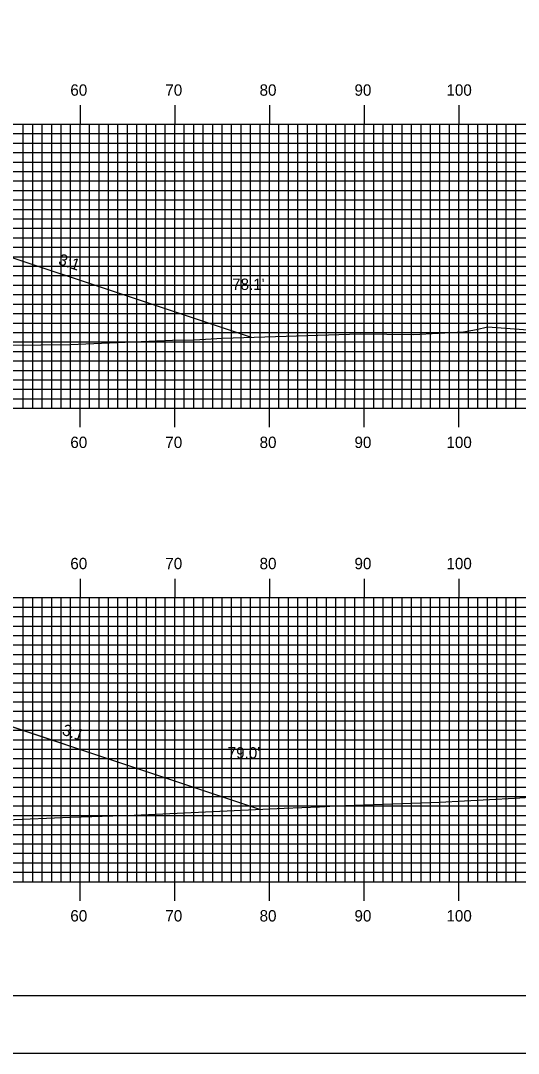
# Model space of a CAD drawing. Extents: x 1762184 to 1762528, y 442591 to 442811.
# Drawn here: x 1762404 to 1762456.5, y 442590.5 to 442699.6 of the extents above; entities that cross this region are included whole.
import ezdxf

# ---------------------------------------------------------------- set-up
doc = ezdxf.new("R2010")
doc.units = 0
for name, color, linetype in [('ANNOTATION', 7, 'Continuous'), ('BORDER', 7, 'Continuous'), ('D_Roadway_Centerline', 7, 'Continuous'), ('D_Roadway_SlopeLines', 7, 'Continuous'), ('D_Text_Standard', 7, 'Continuous'), ('H_V ANNOTATION', 7, 'Continuous'), ('MAJOR', 7, 'Continuous'), ('MINOR', 7, 'Continuous'), ('PLOT BOUNDARY', 7, 'Continuous'), ('S_Roadway_Centerline', 7, 'Continuous')]:
    doc.layers.add(name, color=color, linetype=linetype)

msp = doc.modelspace()

# ---------------------------------------------------------------- linework, layer by layer
at = {"layer": 'BORDER'}
msp.add_lwpolyline([(1762200.67, 442596.67), (1762520.67, 442596.67), (1762520.67, 442806.67), (1762200.67, 442806.67)], close=True, dxfattribs=at)
at = {"layer": 'D_Roadway_Centerline'}
for points in [[(1762388.25, 442679.53), (1762428.32, 442666.17), (1762428.33, 442666.17)], [(1762274.37, 442614.65), (1762275.12, 442614.9), (1762318.99, 442629.52), (1762319.01, 442629.53), (1762325.19, 442631.59), (1762327.27, 442632.28), (1762330.26, 442632.4), (1762330.27, 442632.4), (1762338.27, 442632.72), (1762338.27, 442632.72), (1762350.26, 442633.16), (1762350.27, 442633.16), (1762362.26, 442633.59), (1762362.27, 442633.59), (1762375.55, 442633.06), (1762376.11, 442633.03), (1762385.78, 442630.62), (1762388.12, 442630.03), (1762388.13, 442630.03), (1762429.23, 442616.33)]]:
    msp.add_lwpolyline(points, dxfattribs=at)
at = {"layer": 'D_Roadway_SlopeLines'}
for points in [[(1762376.25, 442682.53), (1762388.25, 442679.53), (1762428.33, 442666.17)], [(1762376.11, 442633.03), (1762388.12, 442630.03), (1762429.23, 442616.33)]]:
    msp.add_lwpolyline(points, dxfattribs=at)
at = {"layer": 'MAJOR'}
for p, q in [((1762410.27, 442690.67), (1762410.27, 442688.67)), ((1762420.27, 442690.67), (1762420.27, 442688.67)), ((1762430.27, 442690.67), (1762430.27, 442688.67)), ((1762440.27, 442690.67), (1762440.27, 442688.67)), ((1762450.27, 442690.67), (1762450.27, 442688.67)), ((1762210.27, 442688.67), (1762490.27, 442688.67)), ((1762210.27, 442688.67), (1762490.27, 442688.67)), ((1762410.27, 442658.67), (1762410.27, 442688.67)), ((1762420.27, 442658.67), (1762420.27, 442688.67)), ((1762430.27, 442658.67), (1762430.27, 442688.67)), ((1762440.27, 442658.67), (1762440.27, 442688.67)), ((1762450.27, 442658.67), (1762450.27, 442688.67)), ((1762210.27, 442683.67), (1762490.27, 442683.67)), ((1762210.27, 442678.67), (1762490.27, 442678.67)), ((1762210.27, 442673.67), (1762490.27, 442673.67)), ((1762210.27, 442668.67), (1762490.27, 442668.67)), ((1762210.27, 442663.67), (1762490.27, 442663.67)), ((1762210.27, 442658.67), (1762490.27, 442658.67)), ((1762210.27, 442658.67), (1762490.27, 442658.67)), ((1762410.27, 442656.66), (1762410.27, 442658.67)), ((1762420.27, 442656.66), (1762420.27, 442658.67)), ((1762430.27, 442656.66), (1762430.27, 442658.67)), ((1762440.27, 442656.66), (1762440.27, 442658.67)), ((1762450.27, 442656.66), (1762450.27, 442658.67)), ((1762410.27, 442640.67), (1762410.27, 442638.67)), ((1762420.27, 442640.67), (1762420.27, 442638.67)), ((1762430.27, 442640.67), (1762430.27, 442638.67)), ((1762440.27, 442640.67), (1762440.27, 442638.67)), ((1762450.27, 442640.67), (1762450.27, 442638.67)), ((1762210.27, 442638.67), (1762490.27, 442638.67)), ((1762210.27, 442638.67), (1762490.27, 442638.67)), ((1762410.27, 442608.67), (1762410.27, 442638.67)), ((1762420.27, 442608.67), (1762420.27, 442638.67)), ((1762430.27, 442608.67), (1762430.27, 442638.67)), ((1762440.27, 442608.67), (1762440.27, 442638.67)), ((1762450.27, 442608.67), (1762450.27, 442638.67)), ((1762210.27, 442633.67), (1762490.27, 442633.67)), ((1762210.27, 442628.67), (1762490.27, 442628.67)), ((1762210.27, 442623.67), (1762490.27, 442623.67)), ((1762210.27, 442618.67), (1762490.27, 442618.67)), ((1762210.27, 442613.67), (1762490.27, 442613.67)), ((1762210.27, 442608.67), (1762490.27, 442608.67)), ((1762210.27, 442608.67), (1762490.27, 442608.67)), ((1762410.27, 442606.66), (1762410.27, 442608.67)), ((1762420.27, 442606.66), (1762420.27, 442608.67)), ((1762430.27, 442606.66), (1762430.27, 442608.67)), ((1762440.27, 442606.66), (1762440.27, 442608.67)), ((1762450.27, 442606.66), (1762450.27, 442608.67))]:
    msp.add_line(p, q, dxfattribs=at)
at = {"layer": 'MINOR'}
for p, q in [((1762404.27, 442658.67), (1762404.27, 442688.67)), ((1762405.27, 442658.67), (1762405.27, 442688.67)), ((1762406.27, 442658.67), (1762406.27, 442688.67)), ((1762407.27, 442658.67), (1762407.27, 442688.67)), ((1762408.27, 442658.67), (1762408.27, 442688.67)), ((1762409.27, 442658.67), (1762409.27, 442688.67)), ((1762411.27, 442658.67), (1762411.27, 442688.67)), ((1762412.27, 442658.67), (1762412.27, 442688.67)), ((1762413.27, 442658.67), (1762413.27, 442688.67)), ((1762414.27, 442658.67), (1762414.27, 442688.67)), ((1762415.27, 442658.67), (1762415.27, 442688.67)), ((1762416.27, 442658.67), (1762416.27, 442688.67)), ((1762417.27, 442658.67), (1762417.27, 442688.67)), ((1762418.27, 442658.67), (1762418.27, 442688.67)), ((1762419.27, 442658.67), (1762419.27, 442688.67)), ((1762421.27, 442658.67), (1762421.27, 442688.67)), ((1762422.27, 442658.67), (1762422.27, 442688.67)), ((1762423.27, 442658.67), (1762423.27, 442688.67)), ((1762424.27, 442658.67), (1762424.27, 442688.67)), ((1762425.27, 442658.67), (1762425.27, 442688.67)), ((1762426.27, 442658.67), (1762426.27, 442688.67)), ((1762427.27, 442658.67), (1762427.27, 442688.67)), ((1762428.27, 442658.67), (1762428.27, 442688.67)), ((1762429.27, 442658.67), (1762429.27, 442688.67)), ((1762431.27, 442658.67), (1762431.27, 442688.67)), ((1762432.27, 442658.67), (1762432.27, 442688.67)), ((1762433.27, 442658.67), (1762433.27, 442688.67)), ((1762434.27, 442658.67), (1762434.27, 442688.67)), ((1762435.27, 442658.67), (1762435.27, 442688.67)), ((1762436.27, 442658.67), (1762436.27, 442688.67)), ((1762437.27, 442658.67), (1762437.27, 442688.67)), ((1762438.27, 442658.67), (1762438.27, 442688.67)), ((1762439.27, 442658.67), (1762439.27, 442688.67)), ((1762441.27, 442658.67), (1762441.27, 442688.67)), ((1762442.27, 442658.67), (1762442.27, 442688.67)), ((1762443.27, 442658.67), (1762443.27, 442688.67)), ((1762444.27, 442658.67), (1762444.27, 442688.67)), ((1762445.27, 442658.67), (1762445.27, 442688.67)), ((1762446.27, 442658.67), (1762446.27, 442688.67)), ((1762447.27, 442658.67), (1762447.27, 442688.67)), ((1762448.27, 442658.67), (1762448.27, 442688.67)), ((1762449.27, 442658.67), (1762449.27, 442688.67)), ((1762451.27, 442658.67), (1762451.27, 442688.67)), ((1762452.27, 442658.67), (1762452.27, 442688.67)), ((1762453.27, 442658.67), (1762453.27, 442688.67)), ((1762454.27, 442658.67), (1762454.27, 442688.67)), ((1762455.27, 442658.67), (1762455.27, 442688.67)), ((1762456.27, 442658.67), (1762456.27, 442688.67)), ((1762210.27, 442687.67), (1762490.27, 442687.67)), ((1762210.27, 442686.67), (1762490.27, 442686.67)), ((1762210.27, 442685.67), (1762490.27, 442685.67)), ((1762210.27, 442684.67), (1762490.27, 442684.67)), ((1762210.27, 442682.67), (1762490.27, 442682.67)), ((1762210.27, 442681.67), (1762490.27, 442681.67)), ((1762210.27, 442680.67), (1762490.27, 442680.67)), ((1762210.27, 442679.67), (1762490.27, 442679.67)), ((1762210.27, 442677.67), (1762490.27, 442677.67)), ((1762210.27, 442676.67), (1762490.27, 442676.67)), ((1762210.27, 442675.67), (1762490.27, 442675.67)), ((1762210.27, 442674.67), (1762490.27, 442674.67)), ((1762210.27, 442672.67), (1762490.27, 442672.67)), ((1762210.27, 442671.67), (1762490.27, 442671.67)), ((1762210.27, 442670.67), (1762490.27, 442670.67)), ((1762210.27, 442669.67), (1762490.27, 442669.67)), ((1762210.27, 442667.67), (1762490.27, 442667.67)), ((1762210.27, 442666.67), (1762490.27, 442666.67)), ((1762210.27, 442665.67), (1762490.27, 442665.67)), ((1762210.27, 442664.67), (1762490.27, 442664.67)), ((1762210.27, 442662.67), (1762490.27, 442662.67)), ((1762210.27, 442661.67), (1762490.27, 442661.67)), ((1762210.27, 442660.67), (1762490.27, 442660.67)), ((1762210.27, 442659.67), (1762490.27, 442659.67)), ((1762404.27, 442608.67), (1762404.27, 442638.67)), ((1762405.27, 442608.67), (1762405.27, 442638.67)), ((1762406.27, 442608.67), (1762406.27, 442638.67)), ((1762407.27, 442608.67), (1762407.27, 442638.67)), ((1762408.27, 442608.67), (1762408.27, 442638.67)), ((1762409.27, 442608.67), (1762409.27, 442638.67)), ((1762411.27, 442608.67), (1762411.27, 442638.67)), ((1762412.27, 442608.67), (1762412.27, 442638.67)), ((1762413.27, 442608.67), (1762413.27, 442638.67)), ((1762414.27, 442608.67), (1762414.27, 442638.67)), ((1762415.27, 442608.67), (1762415.27, 442638.67)), ((1762416.27, 442608.67), (1762416.27, 442638.67)), ((1762417.27, 442608.67), (1762417.27, 442638.67)), ((1762418.27, 442608.67), (1762418.27, 442638.67)), ((1762419.27, 442608.67), (1762419.27, 442638.67)), ((1762421.27, 442608.67), (1762421.27, 442638.67)), ((1762422.27, 442608.67), (1762422.27, 442638.67)), ((1762423.27, 442608.67), (1762423.27, 442638.67)), ((1762424.27, 442608.67), (1762424.27, 442638.67)), ((1762425.27, 442608.67), (1762425.27, 442638.67)), ((1762426.27, 442608.67), (1762426.27, 442638.67)), ((1762427.27, 442608.67), (1762427.27, 442638.67)), ((1762428.27, 442608.67), (1762428.27, 442638.67)), ((1762429.27, 442608.67), (1762429.27, 442638.67)), ((1762431.27, 442608.67), (1762431.27, 442638.67)), ((1762432.27, 442608.67), (1762432.27, 442638.67)), ((1762433.27, 442608.67), (1762433.27, 442638.67)), ((1762434.27, 442608.67), (1762434.27, 442638.67)), ((1762435.27, 442608.67), (1762435.27, 442638.67)), ((1762436.27, 442608.67), (1762436.27, 442638.67)), ((1762437.27, 442608.67), (1762437.27, 442638.67)), ((1762438.27, 442608.67), (1762438.27, 442638.67)), ((1762439.27, 442608.67), (1762439.27, 442638.67)), ((1762441.27, 442608.67), (1762441.27, 442638.67)), ((1762442.27, 442608.67), (1762442.27, 442638.67)), ((1762443.27, 442608.67), (1762443.27, 442638.67)), ((1762444.27, 442608.67), (1762444.27, 442638.67)), ((1762445.27, 442608.67), (1762445.27, 442638.67)), ((1762446.27, 442608.67), (1762446.27, 442638.67)), ((1762447.27, 442608.67), (1762447.27, 442638.67)), ((1762448.27, 442608.67), (1762448.27, 442638.67)), ((1762449.27, 442608.67), (1762449.27, 442638.67)), ((1762451.27, 442608.67), (1762451.27, 442638.67)), ((1762452.27, 442608.67), (1762452.27, 442638.67)), ((1762453.27, 442608.67), (1762453.27, 442638.67)), ((1762454.27, 442608.67), (1762454.27, 442638.67)), ((1762455.27, 442608.67), (1762455.27, 442638.67)), ((1762456.27, 442608.67), (1762456.27, 442638.67)), ((1762210.27, 442637.67), (1762490.27, 442637.67)), ((1762210.27, 442636.67), (1762490.27, 442636.67)), ((1762210.27, 442635.67), (1762490.27, 442635.67)), ((1762210.27, 442634.67), (1762490.27, 442634.67)), ((1762210.27, 442632.67), (1762490.27, 442632.67)), ((1762210.27, 442631.67), (1762490.27, 442631.67)), ((1762210.27, 442630.67), (1762490.27, 442630.67)), ((1762210.27, 442629.67), (1762490.27, 442629.67)), ((1762210.27, 442627.67), (1762490.27, 442627.67)), ((1762210.27, 442626.67), (1762490.27, 442626.67)), ((1762210.27, 442625.67), (1762490.27, 442625.67)), ((1762210.27, 442624.67), (1762490.27, 442624.67)), ((1762210.27, 442622.67), (1762490.27, 442622.67)), ((1762210.27, 442621.67), (1762490.27, 442621.67)), ((1762210.27, 442620.67), (1762490.27, 442620.67)), ((1762210.27, 442619.67), (1762490.27, 442619.67)), ((1762210.27, 442617.67), (1762490.27, 442617.67)), ((1762210.27, 442616.67), (1762490.27, 442616.67)), ((1762210.27, 442615.67), (1762490.27, 442615.67)), ((1762210.27, 442614.67), (1762490.27, 442614.67)), ((1762210.27, 442612.67), (1762490.27, 442612.67)), ((1762210.27, 442611.67), (1762490.27, 442611.67)), ((1762210.27, 442610.67), (1762490.27, 442610.67)), ((1762210.27, 442609.67), (1762490.27, 442609.67))]:
    msp.add_line(p, q, dxfattribs=at)
at = {"layer": 'PLOT BOUNDARY'}
msp.add_lwpolyline([(1762184.48, 442590.55), (1762524.48, 442590.55), (1762524.48, 442810.55), (1762184.48, 442810.55)], close=True, dxfattribs=at)
at = {"layer": 'S_Roadway_Centerline'}
for points in [[(1762399.87, 442665.3), (1762409.23, 442665.41), (1762420.03, 442665.84), (1762422.32, 442665.88), (1762425.29, 442666.07), (1762439.83, 442666.53), (1762445.49, 442666.45), (1762450.76, 442666.72), (1762452.11, 442666.99), (1762453.28, 442667.27), (1762457.58, 442666.94), (1762458.9, 442666.95), (1762461.27, 442667.11), (1762463.39, 442667.18), (1762468.97, 442667.44), (1762480.18, 442667.67), (1762481.78, 442667.72), (1762490.27, 442667.95)], [(1762395.63, 442614.94), (1762409.26, 442615.5), (1762415.97, 442615.69), (1762431.83, 442616.45), (1762435.55, 442616.59), (1762437.19, 442616.69), (1762448.23, 442617.07), (1762456.15, 442617.49), (1762460.13, 442617.74), (1762462.19, 442617.91), (1762464.64, 442617.98), (1762468.88, 442617.9), (1762470.81, 442617.89), (1762472.96, 442618.22), (1762476.25, 442618.35), (1762490.27, 442618.95)]]:
    msp.add_lwpolyline(points, dxfattribs=at)

# ---------------------------------------------------------------- texts
at = {"layer": 'ANNOTATION'}
for rotation, p in [(341.5652, (1762407.89, 442673.89)), (341.565, (1762408.29, 442624.22))]:
    msp.add_text('3:1', height=1.2, rotation=rotation, dxfattribs=at).set_placement(p)
at = {"layer": 'D_Text_Standard'}
for s, p in [("78.1'", (1762426.32, 442671.16)), ("79.0'", (1762425.85, 442621.68))]:
    msp.add_text(s, height=1.2, dxfattribs=at).set_placement(p)
at = {"layer": 'H_V ANNOTATION'}
for s, p in [('60', (1762409.24, 442691.67)), ('70', (1762419.27, 442691.67)), ('80', (1762429.22, 442691.67)), ('90', (1762439.24, 442691.67)), ('100', (1762448.95, 442691.67)), ('60', (1762409.24, 442654.47)), ('70', (1762419.27, 442654.47)), ('80', (1762429.22, 442654.47)), ('90', (1762439.24, 442654.47)), ('100', (1762448.95, 442654.47)), ('60', (1762409.24, 442641.67)), ('70', (1762419.27, 442641.67)), ('80', (1762429.22, 442641.67)), ('90', (1762439.24, 442641.67)), ('100', (1762448.95, 442641.67)), ('60', (1762409.24, 442604.47)), ('70', (1762419.27, 442604.47)), ('80', (1762429.22, 442604.47)), ('90', (1762439.24, 442604.47)), ('100', (1762448.95, 442604.47))]:
    msp.add_text(s, height=1.2, dxfattribs=at).set_placement(p)

doc.saveas('drawing.dxf')
